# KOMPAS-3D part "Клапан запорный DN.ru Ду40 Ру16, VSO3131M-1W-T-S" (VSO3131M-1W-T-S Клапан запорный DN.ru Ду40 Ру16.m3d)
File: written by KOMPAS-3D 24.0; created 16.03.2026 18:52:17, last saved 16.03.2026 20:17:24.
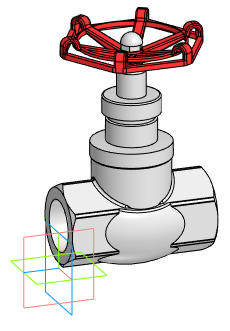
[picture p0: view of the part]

Document properties: Автор: artiomk228874@gmail.com; Полное имя файла: VSO3131M-1W-T-S Клапан запорный DN.ru Ду40 Ру16.cdw

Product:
- Body: Тело 1  | qty 1
    Масса: 1.890349
- Part/product: Клапан запорный DN.ru Ду40 Ру16  | designation VSO3131M-1W-T-S
    Масса: 1.16
    Раздел спецификации: Прочие изделия
    Форматы листов документа: A3
    Примечание: D100-03673
    additional columns: 94d3474e-3e6e-4ddd-ad0b-ef51eb5e31da; VSO3131M-1W-T-S; Клапан запорный DN.ru Ду32 Ру16; Сталь 10 ГОСТ 1050-2013; artiomk228874@gmail.com; c; Шероховатость не задана; Да

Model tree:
1. Операция без истории:1

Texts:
  VSO3131M-1W-T-S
